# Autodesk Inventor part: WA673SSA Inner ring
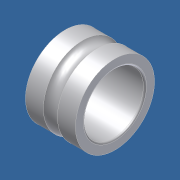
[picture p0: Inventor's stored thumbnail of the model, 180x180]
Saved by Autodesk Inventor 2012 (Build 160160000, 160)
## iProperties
Category: PARTsolutions
Created: 2011-07
Part Number: WA673SSA Inner ring
Catalog Web Link: www.cadenas.de
Description: Six types ir - Metric system sizes
Document SubType Name: Modeling
Designer: PARTsolutions
Density: 1 g/cm^3
Material: Par défaut
NB: WA673SSA Inner ring
NN: Six types ir
NT: Metric system sizes
NBSYN: $ORDER. Inner ring
LINA: WA673SSA Inner ring
SD: 3.0
D: 6
B: 2.0
R: 0.08
ORDER: WA673SSA
CR: 242
COR: 94
CRF: 25
CORF: 9,5
LSG: 60 000
LSO: 71 000
MASS: 0.20
D1: 7.2
D2: 7.2
C1: 0.6
C2: 0.6
ORDER1: 673
WSS: WA673SSA
WDS: SSA
UTWF: FL673
FORSS: FLWA673SA
FORDS: SSA
DA1: 3,6
DA2: 4,1
DA: 5,4
RAS: 0,08
MASS1: 0.26
B1: 2.5
VERS: 3
X: 1.500
N: 9
O: 14.130
RB: 0.444
KT: DUMMY
SUPPLIER: NTN
ARTICLENO: WA673SSA Inner ring
BOMINFO: WA673SSA Inner ring
CREATOR: CADENAS GmbH
PSOL_IDENT_0: {\\10.0.0.251\ps_data\23d-libs\ntn\ball_roller_bearings\miniature_extra_small_bb\metric_system_sizes
PSOL_IDENT_1: \mss_ir.prj},189 {VTYP=3D},{NB=WA673SSA Inner ring},{LINA=WA673SSA Inner ring},{NN=Six types ir},{DA
PSOL_IDENT_2: TE=11.12.2007 08:48:23},{GEOMDATE=28.06.2007 12:57:00},{VERSION=},{LINEID=12590},{LINESUBID=-1},{WBV
PSOL_IDENT_3: AR=}  {NB=WA673SSA Inner ring},{LINA=WA673SSA Inner ring},{KT=DUMMY},{IDNR=},{SD=3.0},{D=6},{B=2.0},
PSOL_IDENT_4: {R=0.08},{ORDER=WA673SSA},{CR=242},{COR=94},{CRF=25},{CORF=9,5},{LSG=60 000},{LSO=71 000},{MASS=0.20
PSOL_IDENT_5: },{D1=7.2},{D2=7.2},{C1=0.6},{C2=0.6},{ORDER1=673},{WSS=WA673SSA},{WDS=SSA},{UTWF=FL673},{FORSS=FLWA
PSOL_IDENT_6: 673SA},{FORDS=SSA},{DA1=3,6},{DA2=4,1},{DA=5,4},{RAS=0,08},{MASS1=0.26},{B1=2.5},{VERS=3},{X=1.5},{N
PSOL_IDENT_7: =9},{O=14.13},{RB=0.444}
Title: WA673SSA Inner ring
Author: Cadenas PARTsolutions
Comments: Metric system sizes
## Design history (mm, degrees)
sketch "Sketch_2"
  geometry: L1 (2.5, 0)-(0, 0); L2 (0, 1.98)-(0, 1.58); L3 (0.08, 1.5)-(2.42, 1.5); L4 (2.5, 1.58)-(2.5, 1.98); L5 (2.5, 1.98)-(1.602, 1.98); L6 (0.898, 1.98)-(0, 1.98); A1 r 0.08 centre (0.08, 1.58) between (0, 1.58) and (0.08, 1.5); A2 r 0.08 centre (2.42, 1.58) between (2.42, 1.5) and (2.5, 1.58); A3 r 0.444 centre (1.25, 2.25) between (0.898, 1.98) and (1.602, 1.98)
  constraints: 12 end point, 6 point on circle, 3 centre point
revolve "Revolution1" sketch "Sketch_2" stored, may be unused: angle "d0" = 360 deg
node "mss_ir_XY"
node "mss_ir_YZ"
node "mss_ir_ZX"
node "mss_ir_X"
node "mss_ir_Y"
node "mss_ir_Z"
node "mss_ir_Center"
node "Solide1"
node "Corps solides"
node "Corps surfaciques"
